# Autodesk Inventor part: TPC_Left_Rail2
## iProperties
Shininess: 64.0
Length Units: 11272
Angle Units: 11279
Time Units: 11290
Mass Units: 11286
Length Display Precision: 3
Angle Display Precision: 2
Compacted: True
Part Number: TPC_Left_Rail2
Document SubType Name: Modeling
Created: 2004-08
Designer: Lori
Manufacturer: Standard
Standards Organization: Custom
Material: Steel, Mild
Density: 0.0
Volumn: 0.0
Area: 0.0
PropertySet Name: Model Information
Control State: 0
Master: False
Checked Out: False
Author: Lori
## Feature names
1. Base1
